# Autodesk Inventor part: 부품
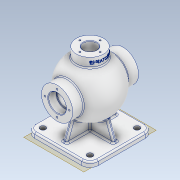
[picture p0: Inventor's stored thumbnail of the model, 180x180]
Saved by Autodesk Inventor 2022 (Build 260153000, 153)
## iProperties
Created: 2024-04
Part Number: 부품
Material: 알루미늄 6061
Document SubType Name: Modeling
Designer: Admin
Density: 2.7 g/cm^3
Appearance: 알루미늄 - 평지
Mass: 2283.99 g
Surface Area: 1052.14 cm^2
Volume: 845.923 cm^3
Author: Admin
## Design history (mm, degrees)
sketch "스케치1"
  geometry: L1 (0, 66.585)-(0, -77.403); L2 (0, 65)-(31, 65); L3 (31, 65)-(31, -65); L4 (31, -65)-(0, -65); L5 (0, -65)-(0, 65); L6 (37.2, 0)-(-6.2, 0) reference; 2 further points
  constraints: 10 end point, 2 parallel, 2 point on line, 1 horizontal, 1 perpendicular, 1 vertical, 1 other
  dimensions: "d0" = 130 distance of L2.end L3.end; "d1" = 62 diameter of L3 L1
revolve "회전1" sketch "스케치1" stored, may be unused: angle "d2" = 90 deg
sketch "스케치2"
  geometry: L1 (0, -91)-(0, 91) reference; L2 (0, 54)-(0, -54); A1 r 54 centre (0, 0) between (0, -54) and (0, 54); 1 further point
  constraints: 2 end point, 2 point on circle, 2 point on line, 1 centre point, 1 coincident, 1 vertical
  dimensions: "d3" = 54 radius of A1
revolve "회전2" sketch "스케치2" stored, may be unused: angle "d4" = 90 deg
node "작업 평면1"
sketch "스케치3"
  geometry: L1 (-62.5, -62.5)-(62.5, -62.5); L2 (62.5, -62.5)-(62.5, 62.5); L3 (62.5, 62.5)-(-62.5, 62.5); L4 (-62.5, 62.5)-(-62.5, -62.5); L5 (-62.5, -62.5)-(62.5, 62.5); L6 (62.5, -62.5)-(-62.5, 62.5); 1 further point
  constraints: 12 end point, 2 midpoint, 2 parallel, 1 horizontal, 1 perpendicular
  dimensions: "d6" = 125 distance of L1.end L2.end; "d7" = 125 distance of L1.start L1.end
extrude "돌출1" join sketch "스케치3" distance "d8" = 10; taper "d9" = 0 deg
sketch "스케치4"
  geometry: L1 (31, -44.215)-(31, -65) reference; L2 (31, -65)-(-31, -65) reference; L3 (-31, -65)-(-31, -44.215) reference; L4 (-31, 44.215)-(-31, 65) reference; L5 (-31, 65)-(31, 65) reference; L6 (31, 65)-(31, 44.215) reference; L7 (-85, 62.5)-(-75, 62.5) reference; L8 (-75, 62.5)-(-75, -62.5) reference; L9 (-75, -62.5)-(-85, -62.5) reference; L10 (-85, -62.5)-(-85, 62.5) reference; L11 (-75, -50.5)-(-38.966, -37.385); L12 (-38.966, -37.385)-(-38.966, 0); L13 (-75, -50.5)-(-75, 0); L14 (-38.966, 0)-(-75, 0); L15 (-38.966, 37.385)-(-38.966, 0); L16 (-75, 50.5)-(-38.966, 37.385); L17 (-75, 50.5)-(-75, 0); A1 r 54 centre (0, 0) between (31, -44.215) and (31, 44.215) reference; A2 r 54 centre (0, 0) between (-31, 44.215) and (-31, -44.215) reference; 1 further point
  constraints: 14 end point, 2 symmetric about line, 1 midpoint, 1 perpendicular, 1 point on circle, 1 point on line, 1 vertical
  dimensions: "d10" = 12 distance from line of L9 L11.start; "d11" = 20 deg angle of L9 L11
  node "절단 모서리 투영1"
node "작업 평면2"
sketch "스케치5"
  geometry: C1 r 27 at (0, 0); 1 further point
  constraints: 1 centre point, 1 coincident
  dimensions: "d13" = 54 diameter of C1
extrude "돌출2" join sketch "스케치5" stored distance "d14" = 10; taper "d15" = 0 deg
extrude "돌출3" join sketch "스케치4" stored distance "d16" = 8; taper "d17" = 0 deg
sketch "스케치6"
  geometry: L1 (-62.5, -85)-(-62.5, -75) reference; L2 (-62.5, -75)-(-4, -75) reference; L3 (-4, -75)-(-4, -53.852) reference; L4 (-27, 46.765)-(-27, 65) reference; L5 (-27, 65)-(27, 65) reference; L6 (27, 65)-(27, 46.765) reference; L7 (4, -53.852)-(4, -75) reference; L8 (4, -75)-(62.5, -75) reference; L9 (62.5, -75)-(62.5, -85) reference; L10 (62.5, -85)-(-62.5, -85) reference; L11 (-50.5, -75)-(-37.385, -38.966); L12 (-37.385, -38.966)-(0, -38.966); L13 (0, -38.966)-(0, -75); L14 (0, -75)-(-50.5, -75); L15 (0, -115)-(0, 95) reference; L16 (37.385, -38.966)-(0, -38.966); L17 (50.5, -75)-(37.385, -38.966); L18 (0, -75)-(50.5, -75); A1 r 54 centre (0, 0) between (-27, 46.765) and (-4, -53.852) reference; A2 r 54 centre (0, 0) between (4, -53.852) and (27, 46.765) reference; 1 further point
  constraints: 14 end point, 2 collinear, 2 symmetric about line, 1 horizontal, 1 perpendicular, 1 point on circle, 1 point on line
  dimensions: "d18" = 12 distance from line of L1 L11.start; "d19" = 20 deg angle of L1 L11
extrude "돌출4" join sketch "스케치6" stored distance "d20" = 8; taper "d21" = 0 deg
sketch "스케치7"
  geometry: L1 (0, -63.282)-(0, 84.465); L2 (0, -65)-(17.5, -65); L3 (17.5, -65)-(17.5, -49.6); L4 (16.9, -49)-(0, -49); L5 (0, -49)-(0, -65); L6 (0, -49)-(15, -49); L7 (15, -49)-(15, 49); L8 (15, 49)-(0, 49); L9 (0, 49)-(0, -49); L10 (0, 49)-(16.9, 49); L11 (17.5, 49.6)-(17.5, 65); L12 (17.5, 65)-(0, 65); L13 (0, 65)-(0, 49); L14 (-115, 0)-(95, 0) reference; L15 (46.765, 27)-(65, 27) reference; L16 (65, 27)-(65, -27) reference; L17 (65, -27)-(46.765, -27) reference; L18 (31, -44.215)-(31, -65) reference; L19 (31, -65)-(-31, -65) reference; L20 (-31, -65)-(-31, -44.215) reference; L21 (-38.966, -37.385)-(-75, -50.5) reference; L22 (-75, -50.5)-(-75, -62.5) reference; L23 (-75, -62.5)-(-85, -62.5) reference; L24 (-85, -62.5)-(-85, 62.5) reference; L25 (-85, 62.5)-(-75, 62.5) reference; L26 (-75, 62.5)-(-75, 50.5) reference; L27 (-75, 50.5)-(-38.966, 37.385) reference; L28 (-31, 44.215)-(-31, 65) reference; L29 (-31, 65)-(31, 65) reference; L30 (31, 65)-(31, 44.215) reference; A1 r 54 centre (0, 0) between (31, -44.215) and (46.765, -27) reference; A2 r 54 centre (0, 0) between (-38.966, -37.385) and (-31, -44.215) reference; A3 r 54 centre (0, 0) between (-31, 44.215) and (-38.966, 37.385) reference; A4 r 54 centre (0, 0) between (46.765, 27) and (31, 44.215) reference; A5 r 0.6 centre (16.9, -49.6) between (17.5, -49.6) and (16.9, -49); A6 r 0.6 centre (16.9, 49.6) between (16.9, 49) and (17.5, 49.6); A7 r 44 centre (0, 0) between (0, -44) and (0, 44); 13 further points
  constraints: 26 end point, 8 point on line, 6 parallel, 6 point on circle, 4 tangent, 3 centre point, 3 horizontal, 3 perpendicular, 1 coincident, 1 collinear, 1 equal radius, 1 vertical, 2 other
  dimensions: "d22" = 30 diameter of L7 L1; "d23" = 35 diameter of L11 L1; "d24" = 35 diameter of L3 L1; "d25" = 16 distance between parallel lines of L4 L2; "d62" = 0.6 radius of A5; "d68" = 44 radius of A7
revolve "회전3" sketch "스케치7" stored, may be unused: angle "d26" = 360 deg
sketch "스케치8"
  geometry: C1 r 13 at (0, 0); 1 further point
  constraints: 1 centre point, 1 coincident
  dimensions: "d27" = 26 diameter of C1
extrude "돌출5" cut sketch "스케치8" stored distance "d28" = 8; taper "d29" = 0 deg
fillet "모깎기1" dims "d30" = 16
sketch "스케치9"
  geometry: L1 (62.5, 46.5)-(62.5, -46.5) reference; L2 (46.5, -62.5)-(-46.5, -62.5) reference; L3 (-62.5, -46.5)-(-62.5, 46.5) reference; L4 (-46.5, 62.5)-(46.5, 62.5) reference; L5 (50.5, -4)-(4, -4) reference; L6 (4, -4)-(4, -50.5) reference; L7 (4, -50.5)-(-4, -50.5) reference; L8 (-4, -50.5)-(-4, -4) reference; L9 (-4, -4)-(-50.5, -4) reference; L10 (-50.5, -4)-(-50.5, 4) reference; L11 (-50.5, 4)-(-4, 4) reference; L12 (-4, 4)-(-4, 50.5) reference; L13 (-4, 50.5)-(4, 50.5) reference; L14 (4, 50.5)-(4, 4) reference; L15 (4, 4)-(50.5, 4) reference; L16 (50.5, 4)-(50.5, -4) reference; C1 r 5.5 at (-46.5, 46.5); C2 r 5.5 at (46.5, 46.5); C3 r 5.5 at (46.5, -46.5); C4 r 5.5 at (-46.5, -46.5); A1 r 16 centre (46.5, 46.5) between (62.5, 46.5) and (46.5, 62.5) reference; A2 r 16 centre (46.5, -46.5) between (46.5, -62.5) and (62.5, -46.5) reference; A3 r 16 centre (-46.5, -46.5) between (-62.5, -46.5) and (-46.5, -62.5) reference; A4 r 16 centre (-46.5, 46.5) between (-46.5, 62.5) and (-62.5, 46.5) reference; 1 further point
  constraints: 4 centre point, 4 coincident, 3 equal radius
  dimensions: "d31" = 11 diameter of C1
extrude "돌출6" cut sketch "스케치9" extent not by distance; stored distance "d32" = 0; taper "d33" = 0 deg
sketch "스케치10"
  geometry: 5 further points
  constraints: 1 vertical alignment, 5 other
  dimensions: "d34" = 24 distance of point (0, 0) point (0, 24); "d37" = 360 deg dimension on point (0, 0) point (0, 24) (derived)
hole "구멍1" sketch "스케치10" at (0, 24), (-24, 0), (0, -24), (24, 0) diameter "d39" = 3.242; stored, may be unused: countersink angle "d43" = 90 deg, drill point angle "d45" = 118 deg; dims "d40" = 12, "d41" = 4, "d42" = 2, "d44" = 15
sketch "스케치11"
  geometry: 5 further points
  constraints: 1 vertical alignment, 5 other
  dimensions: "d46" = 20 distance of point (0, 0) point (0, 20); "d49" = 360 deg dimension on point (0, 0) point (0, 20) (derived)
hole "구멍2" sketch "스케치11" at (0, 20), (-20, 0), (0, -20), (20, 0) diameter "d51" = 3.242; stored, may be unused: countersink angle "d55" = 90 deg, drill point angle "d57" = 118 deg; dims "d52" = 9, "d53" = 4, "d54" = 2, "d56" = 11
fillet "모깎기2" dims "d58" = 3
fillet "모깎기3" dims "d59" = 3
fillet "모깎기4" dims "d60" = 3
fillet "모깎기5" dims "d61" = 3
node "작업 평면4"
sketch "스케치12"
  geometry: L1 (-115, 0)-(95, 0) reference; L2 (65, -27)-(65, 27) reference; 2 further points
  constraints: 1 point on line, 1 other
  dimensions: "d65" = 9 distance from line of point (56, 0) L2
feature "엠보싱1" sketch "스케치12" dims "d6" = 125, "d7" = 125, "d66" = 0.5, "d67" = 0
chamfer "모따기1" distance "d69" = 1; stored, may be unused: second distance "d70" = 2, angle "d71" = 45 deg
fillet "모깎기6" dims "d72" = 3
node "솔리드1"
mirror "미러1"
node "절단 모서리 투영2"
node "절단 모서리 투영3"
node "절단 모서리 투영4"
feature "A9D066F2-1C7D-4E18-AEED-F7BC21143FA4" dims "d39" = 3.242, "d40" = 12, "d41" = 4, "d42" = 2, "d43" = 90 deg, "d44" = 15, "d45" = 118 deg
other parameters: "d5" = -85, "d64" = 74.25
